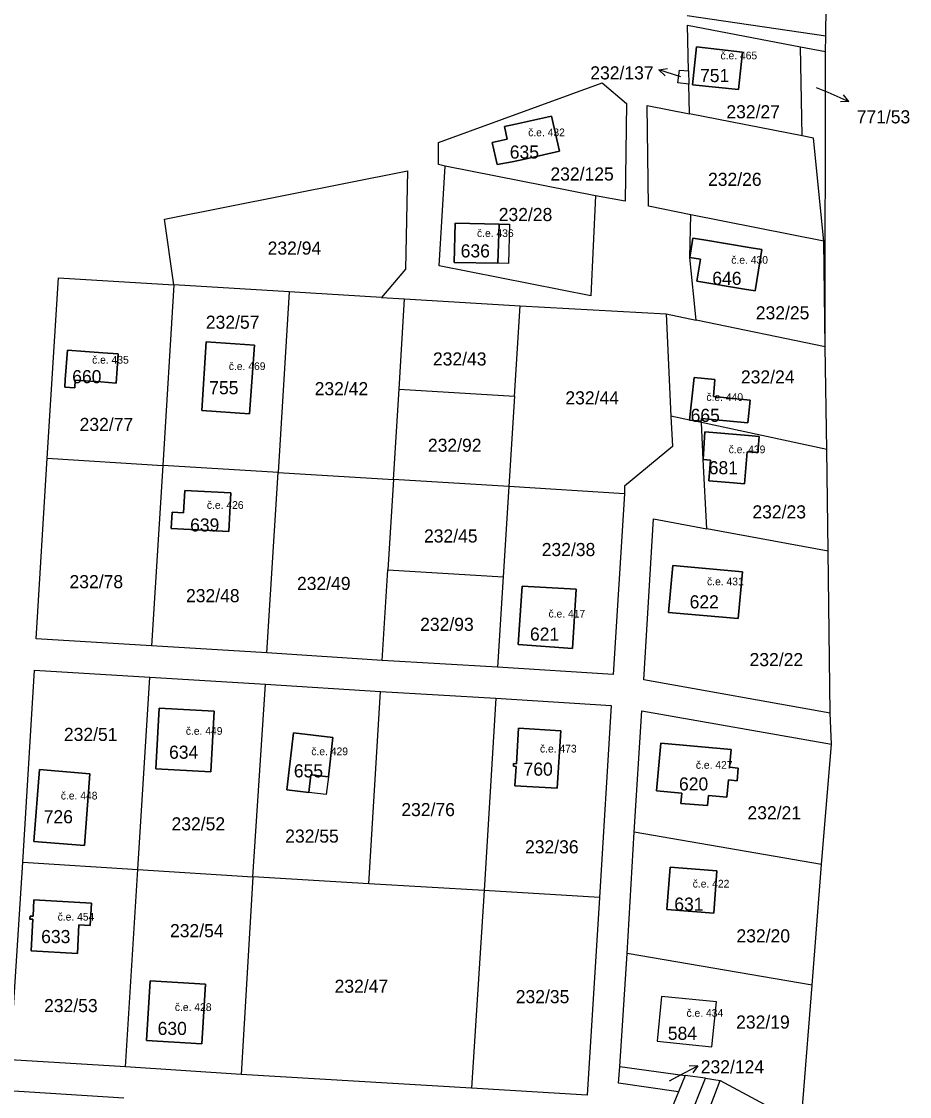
# Model space of a CAD drawing. Extents: x -887272 to -877616, y -1026687 to -1019819.
# Drawn here: x -881922.6 to -881807.4, y -1023755.1 to -1023615.5 of the extents above; entities that cross this region are included whole.
import ezdxf

# ---------------------------------------------------------------- set-up
doc = ezdxf.new("R2010")
doc.units = 0
for name, color, linetype in [('Definiční body', 7, 'Continuous'), ('Hranice parcel', 7, 'Continuous'), ('Parcelní čísla', 7, 'Continuous'), ('Polygon budovy', 7, 'Continuous'), ('Pop  PČ popisy', 7, 'Continuous'), ('Vnitřní kresba', 7, 'Continuous')]:
    doc.layers.add(name, color=color, linetype=linetype)

msp = doc.modelspace()

# ---------------------------------------------------------------- linework, layer by layer
at = {"layer": 'Hranice parcel'}
for p, q in [((-881818.23, -1023617.44), (-881836.19, -1023614.81)), ((-881818.26, -1023619.44), (-881818.23, -1023617.44)), ((-881821.5, -1023618.82), (-881818.26, -1023619.44)), ((-881821.3, -1023630.36), (-881821.5, -1023618.82)), ((-881818.3, -1023657.74), (-881818.26, -1023619.44)), ((-881836.04, -1023621.94), (-881836, -1023623.64)), ((-881835.92, -1023627.51), (-881836, -1023623.64)), ((-881821.3, -1023630.36), (-881835.92, -1023627.51)), ((-881848.1, -1023638.17), (-881867.63, -1023634.29)), ((-881835.87, -1023646.15), (-881835.72, -1023640.61)), ((-881818.49, -1023644.04), (-881835.72, -1023640.61)), ((-881818.3, -1023657.74), (-881818.49, -1023644.04)), ((-881835.03, -1023654.29), (-881835.87, -1023646.15)), ((-881902.81, -1023649.69), (-881904.27, -1023673.15)), ((-881887.84, -1023650.6), (-881902.81, -1023649.69)), ((-881887.84, -1023650.6), (-881889.3, -1023674.08)), ((-881875.88, -1023651.34), (-881887.84, -1023650.6)), ((-881875.88, -1023651.34), (-881872.88, -1023651.52)), ((-881873.59, -1023663.25), (-881872.88, -1023651.52)), ((-881872.88, -1023651.52), (-881857.89, -1023652.44)), ((-881858.62, -1023664.17), (-881857.89, -1023652.44)), ((-881857.89, -1023652.44), (-881838.93, -1023653.49)), ((-881838.93, -1023653.49), (-881835.03, -1023654.29)), ((-881838.93, -1023653.49), (-881838.32, -1023666.74)), ((-881818.3, -1023657.74), (-881835.03, -1023654.29)), ((-881818.1, -1023671.07), (-881818.3, -1023657.74)), ((-881874.31, -1023674.98), (-881873.59, -1023663.25)), ((-881873.59, -1023663.25), (-881858.62, -1023664.17)), ((-881858.62, -1023664.17), (-881859.34, -1023675.9)), ((-881835.89, -1023667.26), (-881838.32, -1023666.74)), ((-881834.34, -1023667.59), (-881835.89, -1023667.26)), ((-881818.1, -1023671.07), (-881834.34, -1023667.59)), ((-881817.93, -1023684.3), (-881818.1, -1023671.07)), ((-881919.24, -1023672.21), (-881904.27, -1023673.15)), ((-881904.27, -1023673.15), (-881905.73, -1023696.58)), ((-881889.3, -1023674.08), (-881904.27, -1023673.15)), ((-881890.75, -1023697.49), (-881889.3, -1023674.08)), ((-881889.3, -1023674.08), (-881874.31, -1023674.98)), ((-881874.31, -1023674.98), (-881875.05, -1023686.72)), ((-881859.34, -1023675.9), (-881874.31, -1023674.98)), ((-881859.34, -1023675.9), (-881860.07, -1023687.62)), ((-881844.35, -1023676.82), (-881859.34, -1023675.9)), ((-881817.93, -1023684.3), (-881833.67, -1023681.37)), ((-881817.63, -1023705.3), (-881817.93, -1023684.3)), ((-881875.79, -1023698.46), (-881875.05, -1023686.72)), ((-881875.05, -1023686.72), (-881860.07, -1023687.62)), ((-881860.07, -1023687.62), (-881860.81, -1023699.34)), ((-881890.75, -1023697.49), (-881905.73, -1023696.58)), ((-881875.79, -1023698.46), (-881890.75, -1023697.49)), ((-881860.81, -1023699.34), (-881875.79, -1023698.46)), ((-881907.51, -1023725.59), (-881905.94, -1023700.64)), ((-881905.94, -1023700.64), (-881890.94, -1023701.57)), ((-881892.55, -1023726.54), (-881890.94, -1023701.57)), ((-881890.94, -1023701.57), (-881876.02, -1023702.5)), ((-881877.53, -1023727.45), (-881876.02, -1023702.5)), ((-881876.02, -1023702.5), (-881861.03, -1023703.38)), ((-881861.03, -1023703.38), (-881862.57, -1023728.35)), ((-881817.47, -1023709.33), (-881817.63, -1023705.3)), ((-881818.77, -1023724.96), (-881817.47, -1023709.33)), ((-881843.99, -1023736.53), (-881843.07, -1023720.74)), ((-881818.77, -1023724.96), (-881843.07, -1023720.74)), ((-881922.43, -1023724.66), (-881907.51, -1023725.59)), ((-881909.11, -1023751.24), (-881907.51, -1023725.59)), ((-881907.51, -1023725.59), (-881892.55, -1023726.54)), ((-881819.99, -1023740.61), (-881818.77, -1023724.96)), ((-881892.55, -1023726.54), (-881894.1, -1023752.21)), ((-881877.53, -1023727.45), (-881892.55, -1023726.54)), ((-881862.57, -1023728.35), (-881877.53, -1023727.45)), ((-881862.57, -1023728.35), (-881864.2, -1023754)), ((-881847.59, -1023729.26), (-881862.57, -1023728.35)), ((-881844.94, -1023751.18), (-881843.99, -1023736.53)), ((-881819.99, -1023740.61), (-881843.99, -1023736.53)), ((-881894.1, -1023752.21), (-881909.11, -1023751.24)), ((-881845.1, -1023753.36), (-881844.94, -1023751.18)), ((-881844.94, -1023751.18), (-881836.45, -1023752.35)), ((-881864.2, -1023754), (-881894.1, -1023752.21)), ((-881841.17, -1023770.99), (-881833.85, -1023752.71)), ((-881836.45, -1023752.35), (-881837.34, -1023754.48)), ((-881833.85, -1023752.71), (-881836.45, -1023752.35)), ((-881833.85, -1023752.71), (-881831.92, -1023752.98)), ((-881837.34, -1023754.48), (-881845.1, -1023753.36)), ((-881839.01, -1023771.53), (-881831.92, -1023752.98)), ((-881831.92, -1023752.98), (-881821.47, -1023758.6))]:
    msp.add_line(p, q, dxfattribs=at)
for points in [[(-881818.23, -1023617.44), (-881818.12, -1023609.45), (-881818.05, -1023604.28), (-881820, -1023599.95)], [(-881836.04, -1023621.94), (-881836.16, -1023616.01), (-881821.5, -1023618.82)], [(-881835.51, -1023623.73), (-881834.99, -1023618.82), (-881829.02, -1023619.5), (-881829.53, -1023624.36), (-881835.51, -1023623.73)], [(-881836, -1023623.64), (-881837.4, -1023623.47), (-881837.2, -1023621.84), (-881836.04, -1023621.94)], [(-881867.63, -1023634.29), (-881868.47, -1023634.08), (-881868.49, -1023631.24), (-881847.25, -1023623.48), (-881844.07, -1023626.16), (-881844.27, -1023638.83), (-881848.1, -1023638.17)], [(-881835.72, -1023640.61), (-881841.21, -1023639.51), (-881841.42, -1023626.42), (-881835.92, -1023627.51)], [(-881853.8, -1023627.8), (-881852.78, -1023632.37), (-881857.48, -1023633.42), (-881858.9, -1023633.73), (-881860.85, -1023634.09), (-881861.52, -1023631.22), (-881859.55, -1023630.8), (-881859.91, -1023629.17), (-881858.49, -1023628.85), (-881853.8, -1023627.8)], [(-881818.49, -1023644.04), (-881819.83, -1023630.65), (-881821.3, -1023630.36)], [(-881902.81, -1023649.69), (-881904.03, -1023641.17), (-881872.52, -1023634.89), (-881872.78, -1023647.68), (-881875.88, -1023651.34)], [(-881848.1, -1023638.17), (-881848.73, -1023651.13), (-881868.37, -1023647.25), (-881867.63, -1023634.29)], [(-881859.4, -1023646.94), (-881860.77, -1023646.91), (-881866.43, -1023646.79), (-881866.32, -1023641.7), (-881860.59, -1023641.82), (-881859.28, -1023641.85), (-881859.4, -1023646.94)], [(-881835.87, -1023646.15), (-881835.49, -1023643.64), (-881834.06, -1023643.88), (-881827.89, -1023644.9), (-881826.5, -1023645.13), (-881827.4, -1023650.5), (-881828.78, -1023650.27), (-881834.95, -1023649.25), (-881834.47, -1023646.39), (-881835.87, -1023646.15)], [(-881919.24, -1023672.21), (-881917.8, -1023648.78), (-881902.81, -1023649.69)], [(-881893.01, -1023666.44), (-881899.19, -1023666.04), (-881898.62, -1023657.09), (-881892.36, -1023657.53), (-881893.01, -1023666.44)], [(-881910.31, -1023662.46), (-881912.31, -1023662.32), (-881915.61, -1023662.09), (-881915.68, -1023663.09), (-881916.98, -1023663), (-881916.91, -1023662), (-881916.63, -1023658.19), (-881912.04, -1023658.52), (-881910.04, -1023658.66), (-881910.31, -1023662.46)], [(-881835.89, -1023667.26), (-881835.32, -1023661.73), (-881832.63, -1023662.02), (-881832.77, -1023664.21), (-881828.02, -1023664.67), (-881828.32, -1023667.62), (-881834.34, -1023667.07), (-881834.35, -1023667.41), (-881835.89, -1023667.26)], [(-881838.32, -1023666.74), (-881838.11, -1023670.71), (-881844.32, -1023675.83), (-881844.35, -1023676.82)], [(-881833.67, -1023681.37), (-881834.11, -1023672.38), (-881834.34, -1023667.59)], [(-881833.91, -1023668.8), (-881828.26, -1023669.28), (-881826.85, -1023669.41), (-881827.03, -1023671.49), (-881828.42, -1023671.37), (-881828.78, -1023675.55), (-881830.19, -1023675.43), (-881833.4, -1023675.15), (-881833.17, -1023672.48), (-881834.11, -1023672.38), (-881833.91, -1023668.8)], [(-881905.73, -1023696.58), (-881920.68, -1023695.66), (-881919.24, -1023672.21)], [(-881895.67, -1023681.74), (-881903.17, -1023681.35), (-881903.05, -1023679.22), (-881901.56, -1023679.3), (-881901.41, -1023676.41), (-881895.41, -1023676.73), (-881895.67, -1023681.74)], [(-881844.35, -1023676.82), (-881845.82, -1023700.28), (-881860.81, -1023699.34)], [(-881817.63, -1023705.3), (-881841.82, -1023700.99), (-881840.58, -1023680.07), (-881833.67, -1023681.37)], [(-881838.07, -1023686.14), (-881829.02, -1023686.98), (-881829.58, -1023693.01), (-881838.61, -1023692.25), (-881838.07, -1023686.14)], [(-881857.61, -1023688.83), (-881850.62, -1023689.23), (-881851.1, -1023696.9), (-881858.12, -1023696.42), (-881857.61, -1023688.83)], [(-881922.43, -1023724.66), (-881920.91, -1023699.74), (-881905.94, -1023700.64)], [(-881861.03, -1023703.38), (-881846.07, -1023704.32), (-881847.59, -1023729.26)], [(-881904.74, -1023704.66), (-881897.61, -1023705.05), (-881898.04, -1023712.93), (-881905.17, -1023712.54), (-881904.74, -1023704.66)], [(-881843.07, -1023720.74), (-881842.08, -1023705.02), (-881817.47, -1023709.33)], [(-881882.17, -1023708.46), (-881882.77, -1023713.58), (-881883.04, -1023715.87), (-881885.3, -1023715.6), (-881888.16, -1023715.26), (-881887.29, -1023707.86), (-881882.17, -1023708.46)], [(-881852.62, -1023707.59), (-881853.07, -1023715.07), (-881858.55, -1023714.73), (-881858.39, -1023712.23), (-881858.75, -1023712.2), (-881858.73, -1023711.85), (-881858.37, -1023711.87), (-881858.08, -1023707.25), (-881852.62, -1023707.59)], [(-881833.55, -1023717.32), (-881837.01, -1023717.03), (-881836.89, -1023715.68), (-881840.18, -1023715.38), (-881839.62, -1023709.21), (-881830.49, -1023710.02), (-881830.7, -1023712.34), (-881829.58, -1023712.44), (-881829.7, -1023714.08), (-881830.85, -1023713.98), (-881831.05, -1023716.21), (-881833.42, -1023715.99), (-881833.55, -1023717.32)], [(-881914.41, -1023722.5), (-881921.01, -1023721.96), (-881920.24, -1023712.63), (-881913.72, -1023713.17), (-881914.41, -1023722.5)], [(-881909.11, -1023751.24), (-881924.05, -1023750.31), (-881922.43, -1023724.66)], [(-881832.35, -1023725.76), (-881832.74, -1023731.26), (-881838.85, -1023730.81), (-881838.42, -1023725.29), (-881832.35, -1023725.76)], [(-881921.34, -1023736.16), (-881921.11, -1023732.06), (-881921.49, -1023732.04), (-881921.47, -1023731.66), (-881921.09, -1023731.68), (-881920.97, -1023729.56), (-881913.52, -1023729.98), (-881913.68, -1023732.89), (-881915.13, -1023732.81), (-881915.33, -1023736.49), (-881921.34, -1023736.16)], [(-881847.59, -1023729.26), (-881849.18, -1023754.92), (-881864.2, -1023754)], [(-881906.38, -1023747.81), (-881905.91, -1023740.07), (-881898.71, -1023740.51), (-881899.18, -1023748.25), (-881906.38, -1023747.81)], [(-881821.47, -1023758.6), (-881821.15, -1023755.32), (-881819.99, -1023740.61)], [(-881839.53, -1023742.09), (-881840.1, -1023747.91), (-881832.99, -1023748.61), (-881832.42, -1023742.78), (-881839.53, -1023742.09)], [(-881925.8, -1023779.26), (-881924.27, -1023754.29), (-881909.32, -1023755.23)], [(-881837.34, -1023754.48), (-881838.77, -1023757.91), (-881839.5, -1023759.51)]]:
    msp.add_lwpolyline(points, dxfattribs=at)
at = {"layer": 'Polygon budovy'}
for points in [[(-881835.51, -1023623.73), (-881829.53, -1023624.36), (-881829.02, -1023619.5), (-881834.99, -1023618.82)], [(-881861.52, -1023631.22), (-881860.85, -1023634.09), (-881858.9, -1023633.73), (-881857.48, -1023633.42), (-881852.78, -1023632.37), (-881853.8, -1023627.8), (-881858.49, -1023628.85), (-881859.91, -1023629.17), (-881859.55, -1023630.8)], [(-881866.43, -1023646.79), (-881860.77, -1023646.91), (-881860.59, -1023641.82), (-881866.32, -1023641.7)], [(-881835.49, -1023643.64), (-881835.87, -1023646.15), (-881834.47, -1023646.39), (-881834.95, -1023649.25), (-881828.78, -1023650.27), (-881827.4, -1023650.5), (-881826.5, -1023645.13), (-881827.89, -1023644.9), (-881834.06, -1023643.88)], [(-881893.01, -1023666.44), (-881892.36, -1023657.53), (-881898.62, -1023657.09), (-881899.19, -1023666.04)], [(-881916.63, -1023658.19), (-881916.91, -1023662), (-881916.98, -1023663), (-881915.68, -1023663.09), (-881915.61, -1023662.09), (-881912.31, -1023662.32), (-881910.31, -1023662.46), (-881910.04, -1023658.66), (-881912.04, -1023658.52)], [(-881835.32, -1023661.73), (-881835.89, -1023667.26), (-881834.35, -1023667.41), (-881834.34, -1023667.07), (-881828.32, -1023667.62), (-881828.02, -1023664.67), (-881832.77, -1023664.21), (-881832.63, -1023662.02)], [(-881833.91, -1023668.8), (-881834.11, -1023672.38), (-881833.17, -1023672.48), (-881833.4, -1023675.15), (-881830.19, -1023675.43), (-881828.78, -1023675.55), (-881828.42, -1023671.37), (-881827.03, -1023671.49), (-881826.85, -1023669.41), (-881828.26, -1023669.28)], [(-881903.17, -1023681.35), (-881895.67, -1023681.74), (-881895.41, -1023676.73), (-881901.41, -1023676.41), (-881901.56, -1023679.3), (-881903.05, -1023679.22)], [(-881829.02, -1023686.98), (-881838.07, -1023686.14), (-881838.61, -1023692.25), (-881829.58, -1023693.01)], [(-881857.61, -1023688.83), (-881858.12, -1023696.42), (-881851.1, -1023696.9), (-881850.62, -1023689.23)], [(-881904.74, -1023704.66), (-881905.17, -1023712.54), (-881898.04, -1023712.93), (-881897.61, -1023705.05)], [(-881887.29, -1023707.86), (-881888.16, -1023715.26), (-881885.3, -1023715.6), (-881885.03, -1023713.32), (-881882.77, -1023713.58), (-881882.17, -1023708.46)], [(-881858.75, -1023712.2), (-881858.39, -1023712.23), (-881858.55, -1023714.73), (-881853.07, -1023715.07), (-881852.62, -1023707.59), (-881858.08, -1023707.25), (-881858.37, -1023711.87), (-881858.73, -1023711.85)], [(-881839.62, -1023709.21), (-881840.18, -1023715.38), (-881836.89, -1023715.68), (-881837.01, -1023717.03), (-881833.55, -1023717.32), (-881833.42, -1023715.99), (-881831.05, -1023716.21), (-881830.85, -1023713.98), (-881829.7, -1023714.08), (-881829.58, -1023712.44), (-881830.7, -1023712.34), (-881830.49, -1023710.02)], [(-881921.01, -1023721.96), (-881914.41, -1023722.5), (-881913.72, -1023713.17), (-881920.24, -1023712.63)], [(-881838.42, -1023725.29), (-881838.85, -1023730.81), (-881832.74, -1023731.26), (-881832.35, -1023725.76)], [(-881921.49, -1023732.04), (-881921.11, -1023732.06), (-881921.34, -1023736.16), (-881915.33, -1023736.49), (-881915.13, -1023732.81), (-881913.68, -1023732.89), (-881913.52, -1023729.98), (-881920.97, -1023729.56), (-881921.09, -1023731.68), (-881921.47, -1023731.66)], [(-881905.91, -1023740.07), (-881906.38, -1023747.81), (-881899.18, -1023748.25), (-881898.71, -1023740.51)], [(-881839.53, -1023742.09), (-881840.1, -1023747.91), (-881832.99, -1023748.61), (-881832.42, -1023742.78)]]:
    msp.add_lwpolyline(points, close=True, dxfattribs=at)
at = {"layer": 'Pop  PČ popisy'}
for p, q in [((-881839.88, -1023621.82), (-881838.78, -1023621.64)), ((-881837.01, -1023622.7), (-881839.88, -1023621.82)), ((-881839.88, -1023621.82), (-881839.07, -1023622.59)), ((-881819.46, -1023624.09), (-881817.97, -1023624.72)), ((-881817.97, -1023624.72), (-881815.21, -1023625.89)), ((-881815.21, -1023625.89), (-881815.93, -1023625.04)), ((-881815.21, -1023625.89), (-881816.33, -1023625.96)), ((-881837.47, -1023752.5), (-881834.82, -1023751.09)), ((-881834.82, -1023751.09), (-881835.94, -1023751.12)), ((-881834.82, -1023751.09), (-881835.47, -1023752)), ((-881838.5, -1023753.04), (-881837.47, -1023752.5))]:
    msp.add_line(p, q, dxfattribs=at)
at = {"layer": 'Vnitřní kresba'}
for p, q in [((-881860.59, -1023641.82), (-881860.77, -1023646.91)), ((-881885.03, -1023713.32), (-881885.3, -1023715.6)), ((-881882.77, -1023713.58), (-881885.03, -1023713.32))]:
    msp.add_line(p, q, dxfattribs=at)

# ---------------------------------------------------------------- texts
at = {"layer": 'Definiční body'}
for s, p in [('č.e. 465', (-881831.88, -1023620.44)), ('č.e. 432', (-881856.84, -1023630.42)), ('č.e. 436', (-881863.48, -1023643.5)), ('č.e. 430', (-881830.48, -1023646.97)), ('č.e. 435', (-881913.43, -1023659.94)), ('č.e. 469', (-881895.69, -1023660.77)), ('č.e. 440', (-881833.71, -1023664.78)), ('č.e. 439', (-881830.82, -1023671.57)), ('č.e. 426', (-881898.53, -1023678.79)), ('č.e. 431', (-881833.63, -1023688.71)), ('č.e. 417', (-881854.2, -1023692.9)), ('č.e. 449', (-881901.27, -1023708.12)), ('č.e. 473', (-881855.31, -1023710.42)), ('č.e. 429', (-881884.98, -1023710.77)), ('č.e. 427', (-881835.08, -1023712.53)), ('č.e. 448', (-881917.49, -1023716.52)), ('č.e. 422', (-881835.49, -1023727.95)), ('č.e. 454', (-881917.9, -1023732.24)), ('č.e. 428', (-881902.69, -1023743.97)), ('č.e. 434', (-881836.29, -1023744.73))]:
    msp.add_text(s, height=1, dxfattribs=at).set_placement(p)
at = {"layer": 'Parcelní čísla'}
for s, p in [('232/137', (-881848.78, -1023623.04)), ('751', (-881834.54, -1023623.39)), ('232/27', (-881831.12, -1023628.09)), ('771/53', (-881814.21, -1023628.75)), ('635', (-881859.23, -1023633.32)), ('232/125', (-881853.95, -1023636.17)), ('232/26', (-881833.5, -1023636.86)), ('232/28', (-881860.66, -1023641.43)), ('232/94', (-881890.65, -1023645.79)), ('636', (-881865.6, -1023646.15)), ('646', (-881832.95, -1023649.71)), ('232/57', (-881898.67, -1023655.41)), ('232/25', (-881827.3, -1023654.19)), ('232/43', (-881869.2, -1023660.18)), ('660', (-881916.01, -1023662.48)), ('232/24', (-881829.23, -1023662.51)), ('755', (-881898.23, -1023663.91)), ('232/42', (-881884.55, -1023664.04)), ('232/44', (-881852.01, -1023665.23)), ('665', (-881835.76, -1023667.5)), ('232/77', (-881915.05, -1023668.68)), ('232/92', (-881869.85, -1023671.38)), ('681', (-881833.41, -1023674.3)), ('232/23', (-881827.74, -1023680.03)), ('639', (-881900.71, -1023681.73)), ('232/45', (-881870.36, -1023683.16)), ('232/38', (-881855.08, -1023684.92)), ('232/78', (-881916.36, -1023689.09)), ('232/49', (-881886.84, -1023689.32)), ('232/48', (-881901.24, -1023690.91)), ('622', (-881835.89, -1023691.71)), ('232/93', (-881870.86, -1023694.63)), ('621', (-881856.61, -1023695.9)), ('232/22', (-881828.11, -1023699.21)), ('232/51', (-881917.09, -1023708.92)), ('634', (-881903.44, -1023711.23)), ('655', (-881887.25, -1023713.65)), ('760', (-881857.44, -1023713.43)), ('620', (-881837.27, -1023715.35)), ('232/76', (-881873.3, -1023718.68)), ('232/21', (-881828.38, -1023719.09)), ('726', (-881919.71, -1023719.61)), ('232/52', (-881903.12, -1023720.53)), ('232/55', (-881888.37, -1023722.12)), ('232/36', (-881857.25, -1023723.51)), ('631', (-881837.88, -1023730.95)), ('232/54', (-881903.32, -1023734.4)), ('633', (-881920.04, -1023735.16)), ('232/20', (-881829.81, -1023735.07)), ('232/47', (-881881.96, -1023741.61)), ('232/35', (-881858.45, -1023742.96)), ('232/53', (-881919.66, -1023744.12)), ('630', (-881904.93, -1023747.09)), ('232/19', (-881829.85, -1023746.26)), ('584', (-881838.72, -1023747.72)), ('232/124', (-881834.44, -1023752.07))]:
    msp.add_text(s, height=1.7, dxfattribs=at).set_placement(p)

doc.saveas('drawing.dxf')
